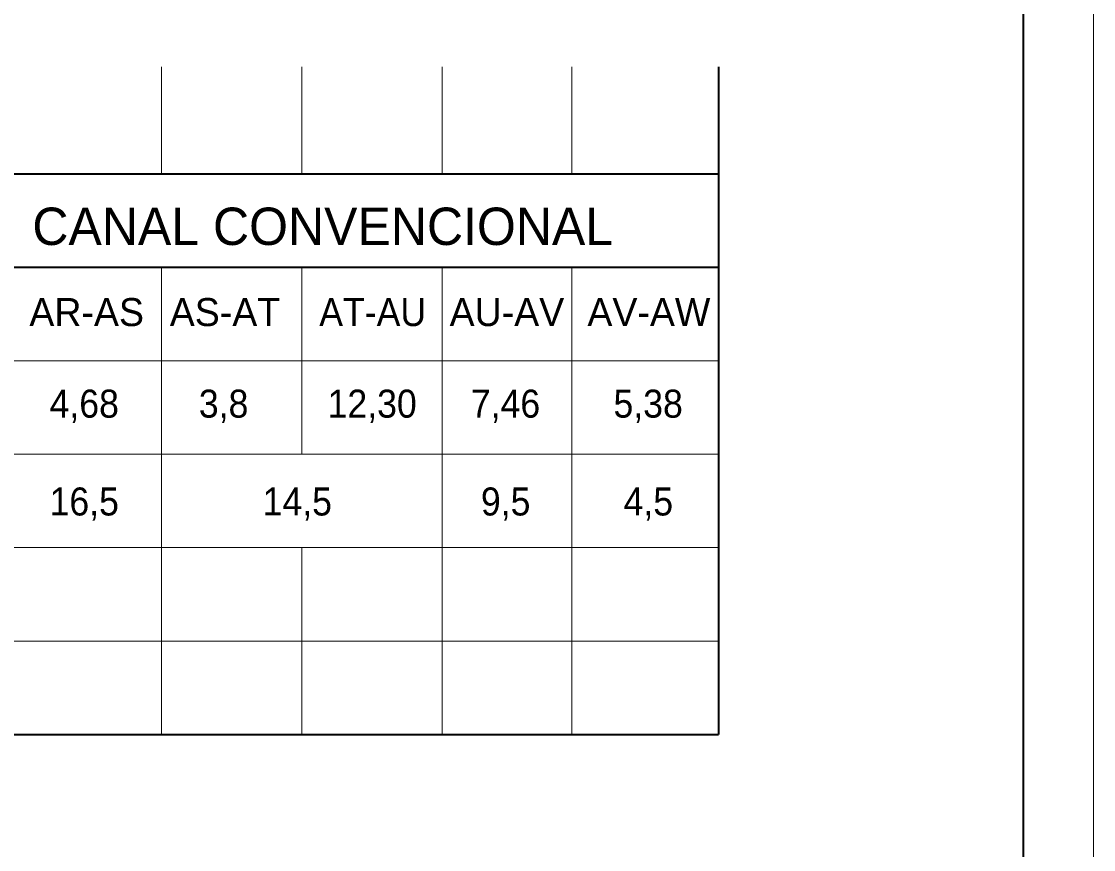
# Model space of a CAD drawing. Extents: x 8458 to 9360, y 19921 to 20366.
# Drawn here: x 9245.4 to 9360.1, y 20009.3 to 20097.9 of the extents above; entities that cross this region are included whole.
import ezdxf

# ---------------------------------------------------------------- set-up
doc = ezdxf.new("R2010")
doc.units = 0
doc.header["$LTSCALE"] = 1.2
doc.layers.add('1', color=7, linetype='Continuous', lineweight=40)
doc.layers.add('5', color=7, linetype='Continuous', lineweight=13)

msp = doc.modelspace()

# ---------------------------------------------------------------- linework, layer by layer
at = {"layer": '1'}
msp.add_line((9352.57, 19928.17), (9352.57, 20358.67), dxfattribs=at)
at = {"layer": '1', "lineweight": 13}
msp.add_lwpolyline([(8457.77, 19920.67), (9360.07, 19920.67), (9360.07, 20366.17), (8457.77, 20366.17)], close=True, dxfattribs=at)
at = {"layer": '5'}
for p, q in [((9260.39, 20093.05), (9260.39, 20081.61)), ((9275.39, 20093.05), (9275.39, 20081.61)), ((9290.39, 20093.05), (9290.39, 20081.61)), ((9304.28, 20093.05), (9304.28, 20081.61)), ((9260.39, 20071.61), (9260.39, 20021.61)), ((9275.39, 20071.61), (9275.39, 20051.61)), ((9290.39, 20071.61), (9290.39, 20021.61)), ((9304.28, 20071.61), (9304.28, 20021.61)), ((8517.12, 20061.6), (9319.97, 20061.61)), ((8517.12, 20051.6), (9319.97, 20051.61)), ((8517.12, 20041.6), (9319.97, 20041.61)), ((8535.69, 20041.6), (9319.97, 20041.61)), ((9275.39, 20041.61), (9275.39, 20021.61)), ((8517.12, 20031.6), (9319.97, 20031.61))]:
    msp.add_line(p, q, dxfattribs=at)
at = {"layer": '5', "lineweight": 35}
for p, q in [((9319.97, 20093.05), (9319.97, 20021.61)), ((8585.69, 20081.6), (9319.97, 20081.61)), ((8585.69, 20071.6), (9319.97, 20071.61)), ((8517.12, 20021.6), (9319.97, 20021.61))]:
    msp.add_line(p, q, dxfattribs=at)

# ---------------------------------------------------------------- texts
at = {"layer": '5'}
for s, height, p in [('CANAL CONVENCIONAL', 4, (9246.56, 20074)), ('AR-AS', 3, (9246.24, 20065.32)), ('AS-AT', 3, (9261.26, 20065.32)), ('AU-AV', 3, (9291.19, 20065.32)), ('AV-AW', 3, (9305.93, 20065.32))]:
    msp.add_text(s, height=height, dxfattribs=at).set_placement(p)
at = {"layer": '5', "width": 0.95}
for s, p in [('AT-AU', (9277.25, 20065.32)), ('4,68', (9248.4, 20055.52)), ('3,8', (9264.37, 20055.52)), ('12,30', (9278.14, 20055.52)), ('7,46', (9293.46, 20055.52)), ('5,38', (9308.72, 20055.52)), ('16,5', (9248.4, 20045.05)), ('14,5', (9271.19, 20045.05)), ('9,5', (9294.54, 20045.05)), ('4,5', (9309.8, 20045.05))]:
    msp.add_text(s, height=3, dxfattribs=at).set_placement(p)

doc.saveas('drawing.dxf')
